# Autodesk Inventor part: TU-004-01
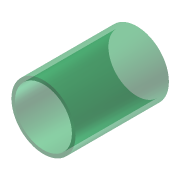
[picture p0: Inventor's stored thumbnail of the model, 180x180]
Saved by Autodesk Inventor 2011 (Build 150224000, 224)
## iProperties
Shininess: 64.0
Angle Display Precision: 2
Document Length Units: 11269
Document Angle Units: 11279
Document Time Units: 11290
Document Mass Units: 11286
Document Length Units Precision: 3
Document Angle Units Precision: 2
Created: 2002-07
Part Number: TU-004-01
Document SubType Name: Modeling
Designer: PN
Description: Cylinder Body- 35 mm
Density: 8.08 g/cm^3
Mass: 184.955 g
Surface Area: 189.956 cm^2
Volume: 22.8904 cm^3
Material: Stainless Steel
Density: 0.0
Volumn: 0.0
Area: 0.0
PropertySet Name: Model Information
Control State: 0
Master: False
Checked Out: False
Stroke_Length: 35.000 mm
Author: PN
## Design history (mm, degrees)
sketch "Sketch1"
  geometry: C1 r 23 at (0, 0); C2 r 20.425 at (0, 0); 1 further point
  constraints: 2 centre point, 2 coincident
  dimensions: "d0" = 46 diameter of C1; "d1" = 40.85 diameter of C2
extrude "Extrusion1" new body sketch "Sketch1" stored distance "d2" = 67 (computed from Stroke_Length); taper "d3" = 0 deg
body "Solid1"
other parameters: "Stroke_Length" = 35 [user parameter; used in 1 equation term]
